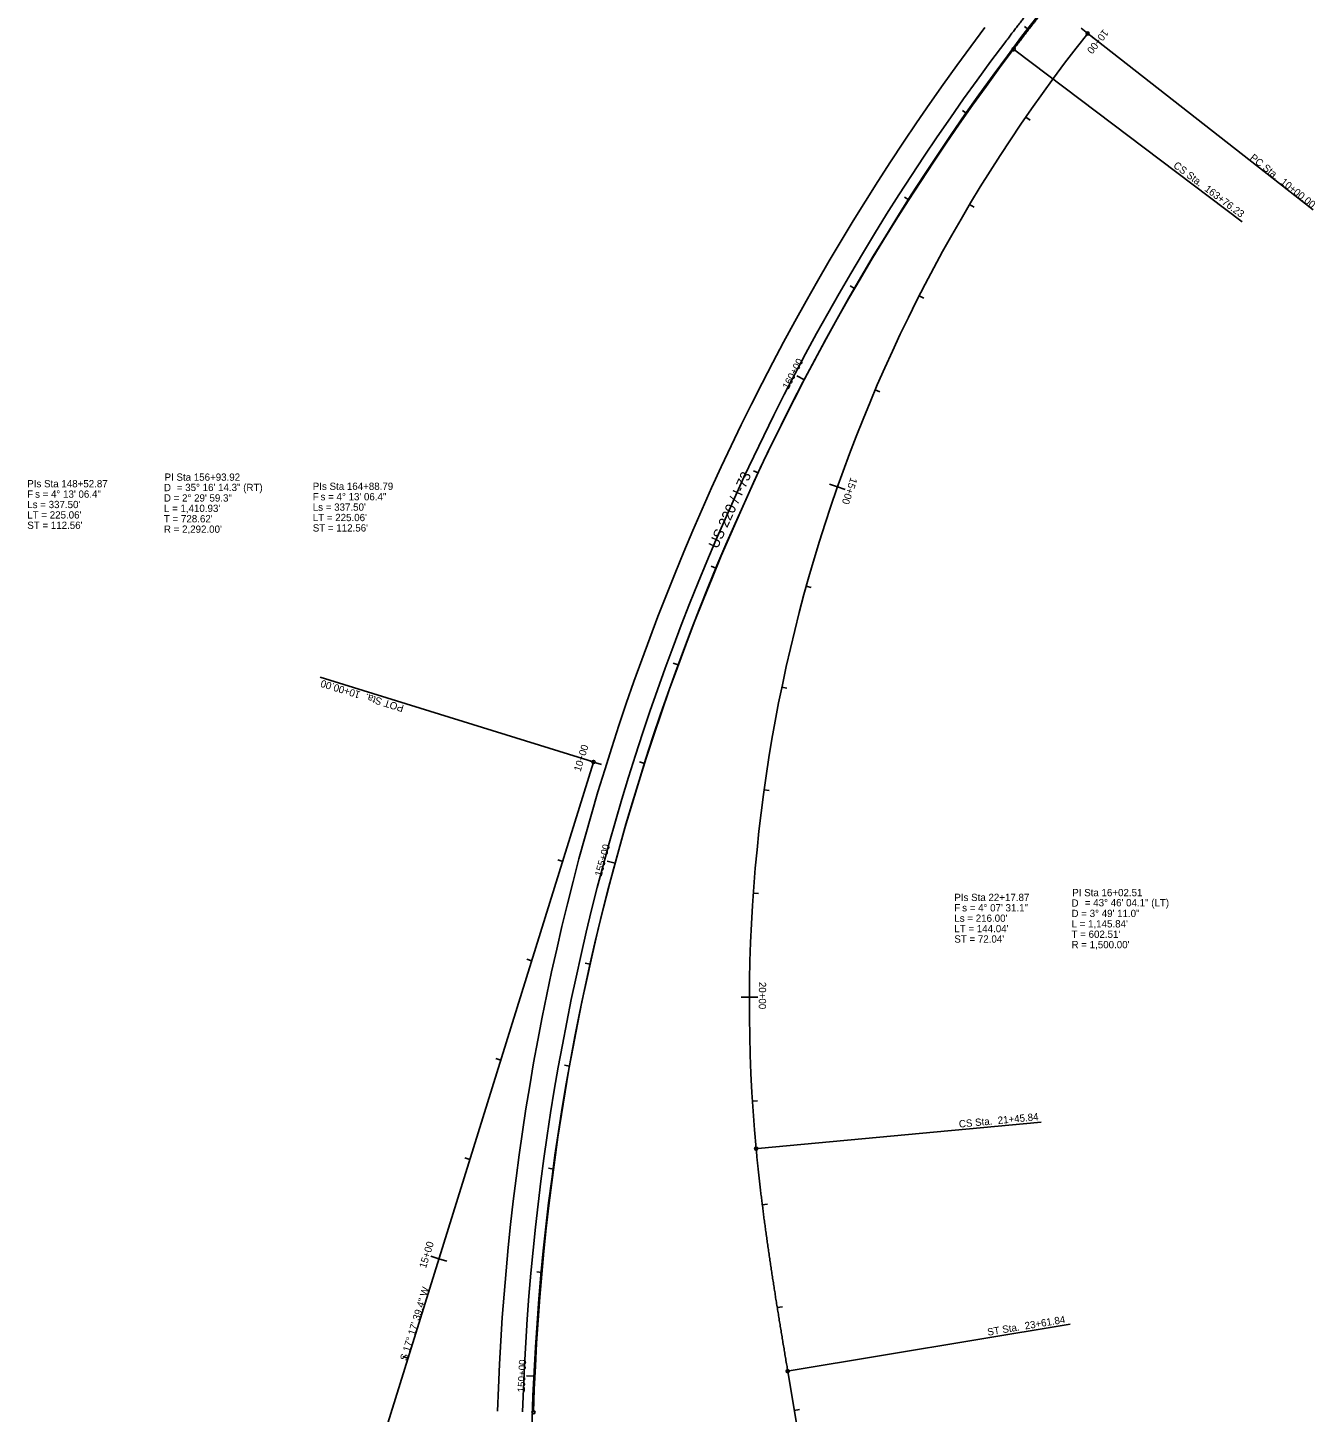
# Model space of a CAD drawing. Extents: x 1722038 to 1726172, y 967033 to 975427.
# Drawn here: x 1723437 to 1724674, y 972370 to 973700 of the extents above; entities that cross this region are included whole.
import ezdxf

# ---------------------------------------------------------------- set-up
doc = ezdxf.new("R2010")
doc.units = 0
for name, color, linetype in [('Prop Horizontal Alignment', 7, 'Continuous'), ('Prop Horizontal Alignment Curve and Spiral Data', 7, 'Continuous'), ('Prop Horizontal Alignment Direction Label', 7, 'Continuous'), ('Prop Horizontal Alignment Station Label', 7, 'Continuous'), ('Prop Horizontal Alignment Tick Label', 7, 'Continuous'), ('Prop Horizontal Alignment Tick Large', 7, 'Continuous'), ('Prop Horizontal Alignment Tick Small', 7, 'Continuous')]:
    doc.layers.add(name, color=color, linetype=linetype)

msp = doc.modelspace()

# ---------------------------------------------------------------- linework, layer by layer
at = {"layer": 'Prop Horizontal Alignment'}
for p, q in [((1723980.3, 972994.6), (1723642.3, 971909)), ((1724166.8, 972409.2), (1724222.8, 972073.2))]:
    msp.add_line(p, q, dxfattribs=at)
for centre, radius, start, end in [((1726238.9, 972290.2), 2318.8, 142.226, 178.7913), ((1726213.5, 972299.3), 2326.5, 142.9705, 178.2412), ((1725630, 972762.4), 1500, 141.5645, 185.3323), ((1726213.5, 972299.3), 2302.5, 142.9705, 178.2412), ((1726213.5, 972299.3), 2292, 142.9705, 178.2412)]:
    msp.add_arc(centre, radius, start, end, dxfattribs=at)
for points in [[(1724592.1, 973945.6), (1724589.1, 973942.1), (1724586, 973938.7), (1724583, 973935.3), (1724580, 973931.8), (1724577, 973928.4), (1724574, 973925), (1724571, 973921.5), (1724568, 973918.1), (1724565, 973914.7), (1724562, 973911.2), (1724559, 973907.8), (1724556, 973904.4), (1724553, 973900.9), (1724550, 973897.5), (1724547, 973894.1), (1724544, 973890.6), (1724541, 973887.2), (1724538, 973883.7), (1724535, 973880.3), (1724532, 973876.8), (1724529, 973873.4), (1724526, 973869.9), (1724523, 973866.5), (1724520.1, 973863), (1724517.1, 973859.6), (1724514.1, 973856.1), (1724511.1, 973852.6), (1724508.1, 973849.2), (1724505.2, 973845.7), (1724502.2, 973842.2), (1724499.2, 973838.8), (1724496.2, 973835.3), (1724493.3, 973831.8), (1724490.3, 973828.3), (1724487.4, 973824.8), (1724484.4, 973821.3), (1724481.5, 973817.9), (1724478.5, 973814.4), (1724475.6, 973810.9), (1724472.6, 973807.4), (1724469.7, 973803.9), (1724466.7, 973800.4), (1724463.8, 973796.8), (1724460.9, 973793.3), (1724458, 973789.8), (1724455.1, 973786.3), (1724452.1, 973782.8), (1724449.2, 973779.2), (1724446.3, 973775.7), (1724443.4, 973772.2), (1724440.5, 973768.6), (1724437.6, 973765.1), (1724434.7, 973761.5), (1724431.9, 973758), (1724429, 973754.4), (1724426.1, 973750.9), (1724423.2, 973747.3), (1724420.4, 973743.7), (1724417.5, 973740.1), (1724414.7, 973736.6), (1724411.8, 973733), (1724409, 973729.4), (1724406.2, 973725.8), (1724403.3, 973722.2), (1724400.5, 973718.6), (1724397.7, 973715), (1724394.9, 973711.4), (1724392.1, 973707.7), (1724389.3, 973704.1), (1724386.5, 973700.5), (1724383.7, 973696.8), (1724380.9, 973693.2), (1724378.2, 973689.5), (1724375.4, 973685.9)], [(1724600, 973938.6), (1724596.9, 973935.2), (1724593.9, 973931.8), (1724590.9, 973928.3), (1724587.9, 973924.9), (1724584.9, 973921.5), (1724581.9, 973918.1), (1724578.9, 973914.6), (1724575.9, 973911.2), (1724572.9, 973907.8), (1724569.9, 973904.3), (1724566.9, 973900.9), (1724563.9, 973897.5), (1724560.9, 973894), (1724557.9, 973890.6), (1724554.9, 973887.2), (1724551.9, 973883.7), (1724548.9, 973880.3), (1724545.9, 973876.8), (1724542.9, 973873.4), (1724539.9, 973869.9), (1724537, 973866.5), (1724534, 973863.1), (1724531, 973859.6), (1724528, 973856.2), (1724525, 973852.7), (1724522, 973849.2), (1724519.1, 973845.8), (1724516.1, 973842.3), (1724513.1, 973838.9), (1724510.2, 973835.4), (1724507.2, 973831.9), (1724504.2, 973828.5), (1724501.3, 973825), (1724498.3, 973821.5), (1724495.4, 973818), (1724492.4, 973814.6), (1724489.5, 973811.1), (1724486.5, 973807.6), (1724483.6, 973804.1), (1724480.7, 973800.6), (1724477.7, 973797.1), (1724474.8, 973793.6), (1724471.9, 973790.1), (1724469, 973786.6), (1724466, 973783.1), (1724463.1, 973779.6), (1724460.2, 973776.1), (1724457.3, 973772.6), (1724454.4, 973769), (1724451.5, 973765.5), (1724448.7, 973762), (1724445.8, 973758.5), (1724442.9, 973754.9), (1724440, 973751.4), (1724437.2, 973747.8), (1724434.3, 973744.3), (1724431.4, 973740.7), (1724428.6, 973737.2), (1724425.7, 973733.6), (1724422.9, 973730), (1724420.1, 973726.5), (1724417.2, 973722.9), (1724414.4, 973719.3), (1724411.6, 973715.7), (1724408.8, 973712.1), (1724406, 973708.5), (1724403.2, 973704.9), (1724400.4, 973701.3), (1724397.6, 973697.7), (1724394.8, 973694.1), (1724392.1, 973690.5), (1724389.3, 973686.8), (1724386.5, 973683.2), (1724383.8, 973679.6)], [(1724166.8, 972409.2), (1724166.4, 972412.1), (1724165.9, 972414.9), (1724165.4, 972417.8), (1724164.9, 972420.7), (1724164.4, 972423.6), (1724164, 972426.5), (1724163.5, 972429.3), (1724163, 972432.2), (1724162.5, 972435.1), (1724162, 972438), (1724161.6, 972440.8), (1724161.1, 972443.7), (1724160.6, 972446.6), (1724160.2, 972449.5), (1724159.7, 972452.4), (1724159.2, 972455.3), (1724158.7, 972458.1), (1724158.3, 972461), (1724157.8, 972463.9), (1724157.3, 972466.8), (1724156.9, 972469.7), (1724156.4, 972472.5), (1724156, 972475.4), (1724155.5, 972478.3), (1724155, 972481.2), (1724154.6, 972484.1), (1724154.1, 972487), (1724153.7, 972489.8), (1724153.2, 972492.7), (1724152.8, 972495.6), (1724152.3, 972498.5), (1724151.9, 972501.4), (1724151.5, 972504.3), (1724151, 972507.1), (1724150.6, 972510), (1724150.2, 972512.9), (1724149.7, 972515.8), (1724149.3, 972518.7), (1724148.9, 972521.6), (1724148.5, 972524.5), (1724148, 972527.4), (1724147.6, 972530.3), (1724147.2, 972533.1), (1724146.8, 972536), (1724146.4, 972538.9), (1724146, 972541.8), (1724145.6, 972544.7), (1724145.2, 972547.6), (1724144.8, 972550.5), (1724144.4, 972553.4), (1724144, 972556.3), (1724143.7, 972559.2), (1724143.3, 972562.1), (1724142.9, 972565), (1724142.6, 972567.9), (1724142.2, 972570.8), (1724141.8, 972573.7), (1724141.5, 972576.5), (1724141.1, 972579.4), (1724140.8, 972582.3), (1724140.4, 972585.2), (1724140.1, 972588.1), (1724139.8, 972591), (1724139.5, 972593.9), (1724139.1, 972596.8), (1724138.8, 972599.7), (1724138.5, 972602.6), (1724138.2, 972605.6), (1724137.9, 972608.5), (1724137.6, 972611.4), (1724137.3, 972614.3), (1724137, 972617.2), (1724136.7, 972620.1), (1724136.5, 972623)]]:
    msp.add_spline(points, degree=3, dxfattribs=at)
at = {"layer": 'Prop Horizontal Alignment Station Label'}
for p, q in [((1724455, 973694.9), (1724671.7, 973525.4)), ((1724385, 973678.7), (1724603.3, 973513.9)), ((1723978.9, 972995), (1723717.7, 973076.3)), ((1724138, 972623.1), (1724410.3, 972648.5)), ((1724168.3, 972409.4), (1724438.1, 972454.4))]:
    msp.add_line(p, q, dxfattribs=at)
for centre in [(1724455, 973694.8), (1724383.8, 973679.6), (1723980.3, 972994.6), (1724136.5, 972623), (1724166.8, 972409.2), (1723922.6, 972369.6)]:
    msp.add_circle(centre, 1.5, dxfattribs=at)
at = {"layer": 'Prop Horizontal Alignment Tick Large'}
for p, q in [((1724455, 973694.8), (1724448.8, 973699.8)), ((1724455, 973694.8), (1724461.3, 973689.9)), ((1724182.8, 973362), (1724175.7, 973365.7)), ((1724214.6, 973259.1), (1724207, 973261.7)), ((1724214.6, 973259.1), (1724222.1, 973256.4)), ((1723980.3, 972994.6), (1723972.7, 972997)), ((1723980.3, 972994.6), (1723987.9, 972992.2)), ((1724000.9, 972897.3), (1723993.2, 972899.4)), ((1724130, 972768.6), (1724122, 972768.6)), ((1724130, 972768.6), (1724138, 972768.6)), ((1723831.6, 972517.2), (1723824, 972519.6)), ((1723831.6, 972517.2), (1723839.3, 972514.8)), ((1723924, 972404.3), (1723916, 972404.6))]:
    msp.add_line(p, q, dxfattribs=at)
at = {"layer": 'Prop Horizontal Alignment Tick Small'}
for p, q in [((1724398.2, 973698.5), (1724394.2, 973701.5)), ((1724338.9, 973618), (1724334.8, 973620.8)), ((1724395.5, 973614.5), (1724399.6, 973611.6)), ((1724283.2, 973534.9), (1724278.9, 973537.6)), ((1724341.5, 973530.4), (1724345.8, 973527.8)), ((1724231.1, 973449.6), (1724226.8, 973452.1)), ((1724293.2, 973442.8), (1724297.6, 973440.5)), ((1724250.8, 973352.2), (1724255.4, 973350.3)), ((1724138.4, 973272.4), (1724133.9, 973274.5)), ((1724097.9, 973181), (1724093.3, 973182.9)), ((1724184.7, 973163.7), (1724189.5, 973162.3)), ((1724061.5, 973087.9), (1724056.8, 973089.6)), ((1724161.1, 973066.5), (1724166, 973065.5)), ((1724029.1, 972993.2), (1724024.4, 972994.8)), ((1724144.1, 972968), (1724149.1, 972967.3)), ((1723950.6, 972899.1), (1723945.8, 972900.6)), ((1724133.7, 972868.5), (1724138.7, 972868.2)), ((1723920.8, 972803.6), (1723916.1, 972805.1)), ((1723977, 972800.2), (1723972.1, 972801.3)), ((1723891.1, 972708.2), (1723886.3, 972709.6)), ((1723957.2, 972702.2), (1723952.3, 972703.1)), ((1724132.9, 972668.7), (1724137.9, 972669)), ((1723861.4, 972612.7), (1723856.6, 972614.2)), ((1723941.8, 972603.4), (1723936.9, 972604.1)), ((1724142.4, 972569.1), (1724147.4, 972569.8)), ((1723930.7, 972504), (1723925.7, 972504.5)), ((1724156.8, 972470.2), (1724161.7, 972471)), ((1723801.9, 972421.7), (1723797.1, 972423.2)), ((1724173.1, 972371.5), (1724178, 972372.4))]:
    msp.add_line(p, q, dxfattribs=at)

# ---------------------------------------------------------------- texts
at = {"layer": 'Prop Horizontal Alignment Curve and Spiral Data'}
for s, p in [('PI Sta 156+93.92', (1723568.1, 973264.9)), ('PIs Sta 148+52.87', (1723436.2, 973258.6)), ('F', (1723436.2, 973248.6)), ('s = 4%%d 13\' 06.4"', (1723443.7, 973248.6)), ('D', (1723567.5, 973254.9)), ('= 35%%d 16\' 14.3" (RT)', (1723579.9, 973255)), ('PIs Sta 164+88.79', (1723710.5, 973256.1)), ('F', (1723710.5, 973246.1)), ('s = 4%%d 13\' 06.4"', (1723718, 973246.1)), ("Ls = 337.50'", (1723436.2, 973238.6)), ('D = 2%%d 29\' 59.3"', (1723567.5, 973244.9)), ("L = 1,410.93'", (1723567.5, 973234.9)), ("Ls = 337.50'", (1723710.5, 973236.1)), ("LT = 225.06'", (1723436.2, 973228.6)), ("T = 728.62'", (1723567.5, 973224.9)), ("LT = 225.06'", (1723710.5, 973226.1)), ("ST = 112.56'", (1723436.2, 973218.6)), ("R = 2,292.00'", (1723567.5, 973214.9)), ("ST = 112.56'", (1723710.5, 973216.1)), ('PIs Sta 22+17.87', (1724326.9, 972861)), ('PI Sta 16+02.51', (1724440.2, 972865.6)), ('F', (1724326.9, 972851)), ('s = 4%%d 07\' 31.1"', (1724334.4, 972851)), ('D', (1724439.5, 972855.6)), ('= 43%%d 46\' 04.1" (LT)', (1724452.3, 972855.9)), ("Ls = 216.00'", (1724326.9, 972841)), ('D = 3%%d 49\' 11.0"', (1724439.5, 972845.6)), ("L = 1,145.84'", (1724439.5, 972835.6)), ("ST = 72.04'", (1724326.9, 972821)), ("LT = 144.04'", (1724326.9, 972831)), ("T = 602.51'", (1724439.5, 972825.6)), ("R = 1,500.00'", (1724439.5, 972815.6))]:
    msp.add_text(s, height=7, dxfattribs=at).set_placement(p)
at = {"layer": 'Prop Horizontal Alignment Direction Label'}
msp.add_text('S 17%%d 17\' 39.4" W', height=7, rotation=72.7057, dxfattribs=at).set_placement((1723800.8, 972418.7))
at = {"layer": 'Prop Horizontal Alignment Station Label'}
for s, rotation, p in [('PC Sta.  10+00.00', 321.5645, (1724610.3, 973574.2)), ('CS Sta.  163+76.23', 322.9705, (1724536.7, 973566.7)), ('POT Sta.  10+00.00', 162.7057, (1723798.6, 973049.1)), ('CS Sta.  21+45.84', 5.3323, (1724331.6, 972643.2)), ('ST Sta.  23+61.84', 9.4576, (1724359.2, 972443.2))]:
    msp.add_text(s, height=7, rotation=rotation, dxfattribs=at).set_placement(p)
at = {"layer": 'Prop Horizontal Alignment Tick Label'}
for s, height, rotation, p in [('10+00', 7, 231.5645, (1724470.2, 973699.4)), ('160+00', 7, 62.3756, (1724167.5, 973352.2)), ('US 220 / I-73', 10, 65.5337, (1724099.4, 973198.9)), ('15+00', 7, 250.6631, (1724227.4, 973268.5)), ('10+00', 7, 72.7057, (1723967.8, 972984.9)), ('155+00', 7, 74.8747, (1723988, 972884.1)), ('20+00', 7, 269.7617, (1724139.1, 972783.3)), ('15+00', 7, 72.7057, (1723819.2, 972507.4)), ('150+00', 7, 87.3738, (1723914.2, 972388.7))]:
    msp.add_text(s, height=height, rotation=rotation, dxfattribs=at).set_placement(p)

doc.saveas('drawing.dxf')
